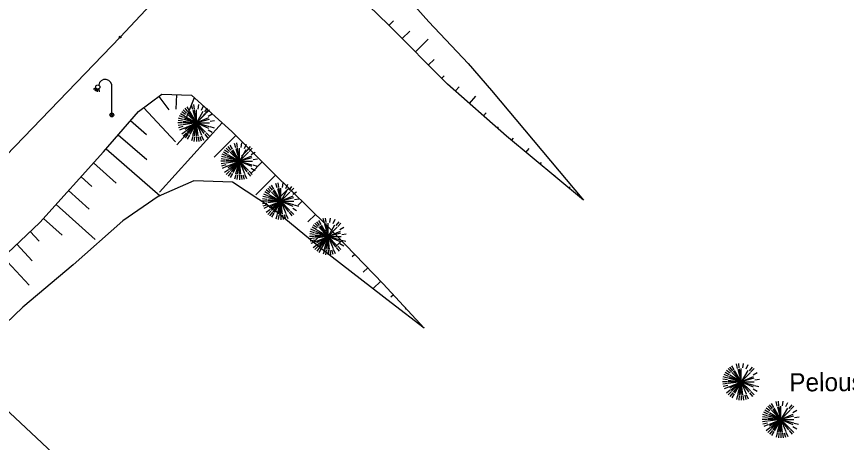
# Model space of a CAD drawing. Extents: x 344013 to 344423, y 298505 to 298795.
# Drawn here: x 344132.25 to 344176.66, y 298618.28 to 298641.08 of the extents above; entities that cross this region are included whole.
import ezdxf

# ---------------------------------------------------------------- set-up
doc = ezdxf.new("R2010")
doc.units = 0
for name, color, linetype in [('Default', 7, 'Continuous'), ('PS_BOLT', 7, 'Continuous'), ('PS_CONST', 7, 'Continuous'), ('RES_ELECTRICITE', 7, 'Continuous'), ('TOPO_POINT', 7, 'Continuous'), ('TOPO_TALUS-TERRAIN NATUREL', 7, 'Continuous'), ('VOIRIE_BORDURE', 7, 'Continuous'), ('VOIRIE_ESPACE VERT', 7, 'Continuous')]:
    doc.layers.add(name, color=color, linetype=linetype)

# ---------------------------------------------------------------- blocks, each defined once
blk = doc.blocks.new('EDF1')
at = {"layer": 'Default'}
for points in [[(-0.855, 1.462), (-0.985, 1.373)], [(-0.83, 1.422), (-0.931, 1.303)], [(-0.793, 1.397), (-0.86, 1.257)], [(-0.753, 1.388), (-0.781, 1.235)], [(-0.701, 1.4), (-0.684, 1.241)], [(0, 0.1), (0, 1.5)]]:
    blk.add_lwpolyline(points, dxfattribs=at)
for centre, radius in [((-0.75, 1.5), 0.112), ((0, 0), 0.1)]:
    blk.add_circle(centre, radius, dxfattribs=at)
blk.add_arc((-0.35, 1.55), 0.354, 351.8699, 171.8699, dxfattribs=at)
blk = doc.blocks.new('POINT_DISPLAY')
at = {"layer": 'Default'}
blk.add_circle((0, 0), 0.05, dxfattribs=at)
blk = doc.blocks.new('ARB2')
at = {"layer": 'Default'}
for p, q in [((-0.181, 0.716), (-0.244, 0.956)), ((-0.088, 0.736), (-0.119, 0.983)), ((0.106, 0.736), (0.144, 0.983)), ((0.287, 0.684), (0.388, 0.914)), ((-0.631, 0.373), (-0.844, 0.497)), ((-0.575, 0.453), (-0.775, 0.605)), ((-0.513, 0.525), (-0.688, 0.702)), ((-0.438, 0.589), (-0.588, 0.786)), ((-0.356, 0.642), (-0.481, 0.858)), ((0.456, 0.589), (0.612, 0.786)), ((0.531, 0.525), (0.706, 0.702)), ((0.65, 0.373), (0.862, 0.497)), ((-0.731, 0), (-0.981, 0)), ((-0.725, 0.1), (-0.969, 0.133)), ((-0.706, 0.195), (-0.944, 0.259)), ((-0.675, 0.286), (-0.9, 0.381)), ((0.744, 0.1), (0.987, 0.133)), ((-0.725, -0.1), (-0.969, -0.133)), ((-0.706, -0.195), (-0.944, -0.259)), ((-0.675, -0.287), (-0.9, -0.383)), ((0.65, -0.373), (0.862, -0.498)), ((0.725, -0.195), (0.963, -0.259)), ((-0.575, -0.455), (-0.775, -0.605)), ((-0.513, -0.527), (-0.688, -0.702)), ((-0.438, -0.591), (-0.588, -0.787)), ((-0.356, -0.644), (-0.481, -0.859)), ((-0.181, -0.717), (-0.244, -0.956)), ((-0.088, -0.737), (-0.119, -0.983)), ((0.013, -0.741), (0.013, -0.989)), ((0.106, -0.737), (0.144, -0.983)), ((0.2, -0.717), (0.263, -0.956)), ((0.287, -0.686), (0.388, -0.916)), ((0.456, -0.591), (0.612, -0.787)), ((0.531, -0.527), (0.706, -0.702))]:
    blk.add_line(p, q, dxfattribs=at)
for points in [[(-0.688, 0.091), (0.013, 0), (-0.338, 0.608)], [(-0.487, 0.495), (0.013, 0), (-0.669, 0.181)], [(-0.419, 0.556), (0.013, 0), (-0.638, 0.269)], [(-0.169, 0.677), (0.013, 0), (-0.6, 0.35)], [(0.013, 0.008), (0.013, 0), (-0.081, 0.695)], [(0.362, 0.608), (0.013, 0), (0.013, 0.702)], [(0.656, 0.269), (0.013, 0), (0.506, 0.495)], [(-0.487, -0.497), (0.013, 0), (-0.694, 0)], [(-0.638, -0.269), (0.013, 0), (-0.688, -0.092)], [(-0.169, -0.678), (0.013, 0), (-0.6, -0.352)], [(-0.544, -0.428), (0.013, 0), (-0.338, -0.608)], [(-0.081, -0.695), (0.013, 0), (-0.419, -0.558)], [(0.013, -0.702), (0.013, 0), (0, 0)], [(0.688, 0.181), (0.013, 0), (0.713, 0)], [(0.438, -0.558), (0.013, 0), (0.656, -0.269)], [(0.506, -0.497), (0.013, 0), (0.688, -0.181)], [(0.1, -0.695), (0.013, 0), (0.281, -0.648)], [(0.019, 0), (0.013, 0), (0.013, -0.009)]]:
    blk.add_lwpolyline(points, dxfattribs=at)

msp = doc.modelspace()

# ---------------------------------------------------------------- linework, layer by layer
at = {"layer": 'PS_BOLT'}
msp.add_lwpolyline([(344173.444, 298593.641), (344172.427, 298592.568), (344178.462, 298586.939), (344174.396, 298582.587), (344168.376, 298588.228), (344167.085, 298586.853), (344168.386, 298585.586), (344159.324, 298576.069), (344121.411, 298611.054), (344130.716, 298620.945), (344149.461, 298603.379), (344147.717, 298601.519)], dxfattribs=at)
at = {"layer": 'TOPO_TALUS-TERRAIN NATUREL'}
for p, q in [((344152.187, 298640.611), (344152.42, 298640.844)), ((344152.893, 298639.903), (344153.292, 298640.301)), ((344153.599, 298639.194), (344154.281, 298639.875)), ((344154.305, 298638.486), (344154.597, 298638.777)), ((344155.011, 298637.777), (344155.136, 298637.902)), ((344155.741, 298637.094), (344155.94, 298637.319)), ((344140.813, 298636.897), (344140.78, 298636.113)), ((344139.855, 298636.805), (344140.397, 298636.076)), ((344141.761, 298636.73), (344141.289, 298635.572)), ((344156.489, 298636.43), (344156.83, 298636.814)), ((344139.052, 298636.207), (344140.755, 298634.376)), ((344142.504, 298636.061), (344140.83, 298634.203)), ((344138.347, 298635.505), (344139.198, 298634.769)), ((344157.237, 298635.766), (344157.383, 298635.93)), ((344143.247, 298635.391), (344139.9, 298631.675)), ((344157.985, 298635.101), (344158.047, 298635.172)), ((344137.693, 298634.749), (344139.218, 298633.43)), ((344143.98, 298634.711), (344142.822, 298633.548)), ((344158.74, 298634.446), (344158.843, 298634.57)), ((344137.039, 298633.992), (344139.935, 298631.487)), ((344144.689, 298634.005), (344144.289, 298633.603)), ((344159.509, 298633.807), (344159.685, 298634.018)), ((344145.397, 298633.299), (344144.783, 298632.682)), ((344136.373, 298633.246), (344137.589, 298632.152)), ((344160.278, 298633.167), (344160.353, 298633.257)), ((344135.704, 298632.502), (344136.281, 298631.982)), ((344146.106, 298632.593), (344145.064, 298631.537)), ((344161.048, 298632.527), (344161.08, 298632.566)), ((344161.817, 298631.888), (344161.871, 298631.954)), ((344135.035, 298631.758), (344136.132, 298630.771)), ((344146.818, 298631.891), (344146.324, 298631.39)), ((344147.531, 298631.188), (344147.32, 298630.975)), ((344134.366, 298631.014), (344136.45, 298629.14)), ((344133.697, 298630.271), (344134.687, 298629.381)), ((344148.243, 298630.486), (344147.843, 298630.081)), ((344148.952, 298629.781), (344148.179, 298629.03)), ((344132.986, 298629.569), (344133.466, 298629.057)), ((344132.257, 298628.884), (344133.078, 298628.009)), ((344149.649, 298629.064), (344149.32, 298628.743)), ((344131.527, 298628.199), (344132.932, 298626.703)), ((344150.347, 298628.346), (344150.206, 298628.21)), ((344151.044, 298627.629), (344150.804, 298627.396)), ((344151.741, 298626.912), (344151.332, 298626.514)), ((344152.423, 298626.18), (344152.279, 298626.047)), ((344153.102, 298625.446), (344153.057, 298625.404)), ((344153.781, 298624.711), (344153.754, 298624.686))]:
    msp.add_line(p, q, dxfattribs=at)
for points in [[(344162.586, 298631.249), (344158.463, 298634.677), (344155.322, 298637.466), (344152.157, 298640.641), (344150.03, 298642.712), (344148.876, 298643.869), (344148.225, 298645.042), (344148.989, 298646.167), (344150.999, 298648.31), (344152.976, 298650.281), (344154.876, 298652.174), (344156.31, 298653.84), (344157.421, 298655.01), (344158.446, 298655.921), (344159.147, 298656.242), (344160.098, 298656.281)], [(344160.098, 298656.281), (344158.45, 298653.962), (344154.227, 298648.857), (344151.775, 298646.036), (344151.324, 298644.439), (344151.952, 298643.242), (344152.321, 298642.95), (344152.643, 298643.115), (344152.674, 298642.658), (344154.315, 298640.791), (344156.42, 298638.569), (344157.669, 298637.128), (344162.586, 298631.249)], [(344124.346, 298624.984), (344126.33, 298625.357), (344128.607, 298626.165), (344131.049, 298627.75), (344133.499, 298630.05), (344136.91, 298633.844), (344138.778, 298636.003), (344140.023, 298636.93), (344141.613, 298636.864), (344143.764, 298634.926), (344146.016, 298632.683), (344148.833, 298629.903), (344151.879, 298626.77), (344154.069, 298624.399)], [(344154.069, 298624.399), (344152.293, 298625.755), (344148.595, 298628.63), (344145.956, 298630.806), (344143.812, 298632.217), (344141.743, 298632.29), (344139.831, 298631.436), (344137.933, 298630.141), (344135.272, 298627.787), (344132.577, 298625.511), (344130.725, 298623.759), (344129.654, 298622.612), (344128.717, 298621.914), (344128.286, 298620.948)]]:
    msp.add_lwpolyline(points, dxfattribs=at)
at = {"layer": 'VOIRIE_BORDURE'}
msp.add_lwpolyline([(344120.412, 298621.951), (344137.791, 298639.981), (344144.065, 298646.663), (344154.783, 298657.656), (344157.662, 298660.576), (344158.342, 298661.39), (344163.216, 298666.766), (344163.731, 298667.308), (344164.688, 298668.072), (344165.676, 298668.545), (344166.447, 298668.825), (344167.222, 298669.059), (344168.509, 298669.289), (344169.751, 298669.392), (344170.251, 298669.414), (344170.803, 298669.375), (344172.06, 298669.227), (344173.884, 298668.877), (344175.641, 298668.318), (344176.928, 298667.79), (344178.107, 298666.872), (344194.798, 298651.17), (344217.989, 298629.411), (344240.944, 298607.781)], dxfattribs=at)

# ---------------------------------------------------------------- block references
at = {"layer": 'RES_ELECTRICITE'}
msp.add_blockref('EDF1', (344137.347, 298635.809), dxfattribs=at)
at = {"layer": 'TOPO_POINT'}
for p in [(344137.791, 298639.981), (344137.347, 298635.809), (344141.861, 298635.381), (344144.161, 298633.329), (344146.378, 298631.19), (344148.907, 298629.309), (344171.021, 298621.529), (344173.142, 298619.509)]:
    msp.add_blockref('POINT_DISPLAY', p, dxfattribs=at)
at = {"layer": 'VOIRIE_ESPACE VERT'}
for p in [(344141.861, 298635.381), (344144.161, 298633.329), (344146.378, 298631.19), (344148.907, 298629.309), (344171.021, 298621.529), (344173.142, 298619.509)]:
    msp.add_blockref('ARB2', p, dxfattribs=at)

# ---------------------------------------------------------------- texts
at = {"layer": 'PS_CONST'}
msp.add_text('Pelouse', height=0.9758, rotation=0.3665, dxfattribs=at).set_placement((344173.608, 298621.005))

doc.saveas('drawing.dxf')
